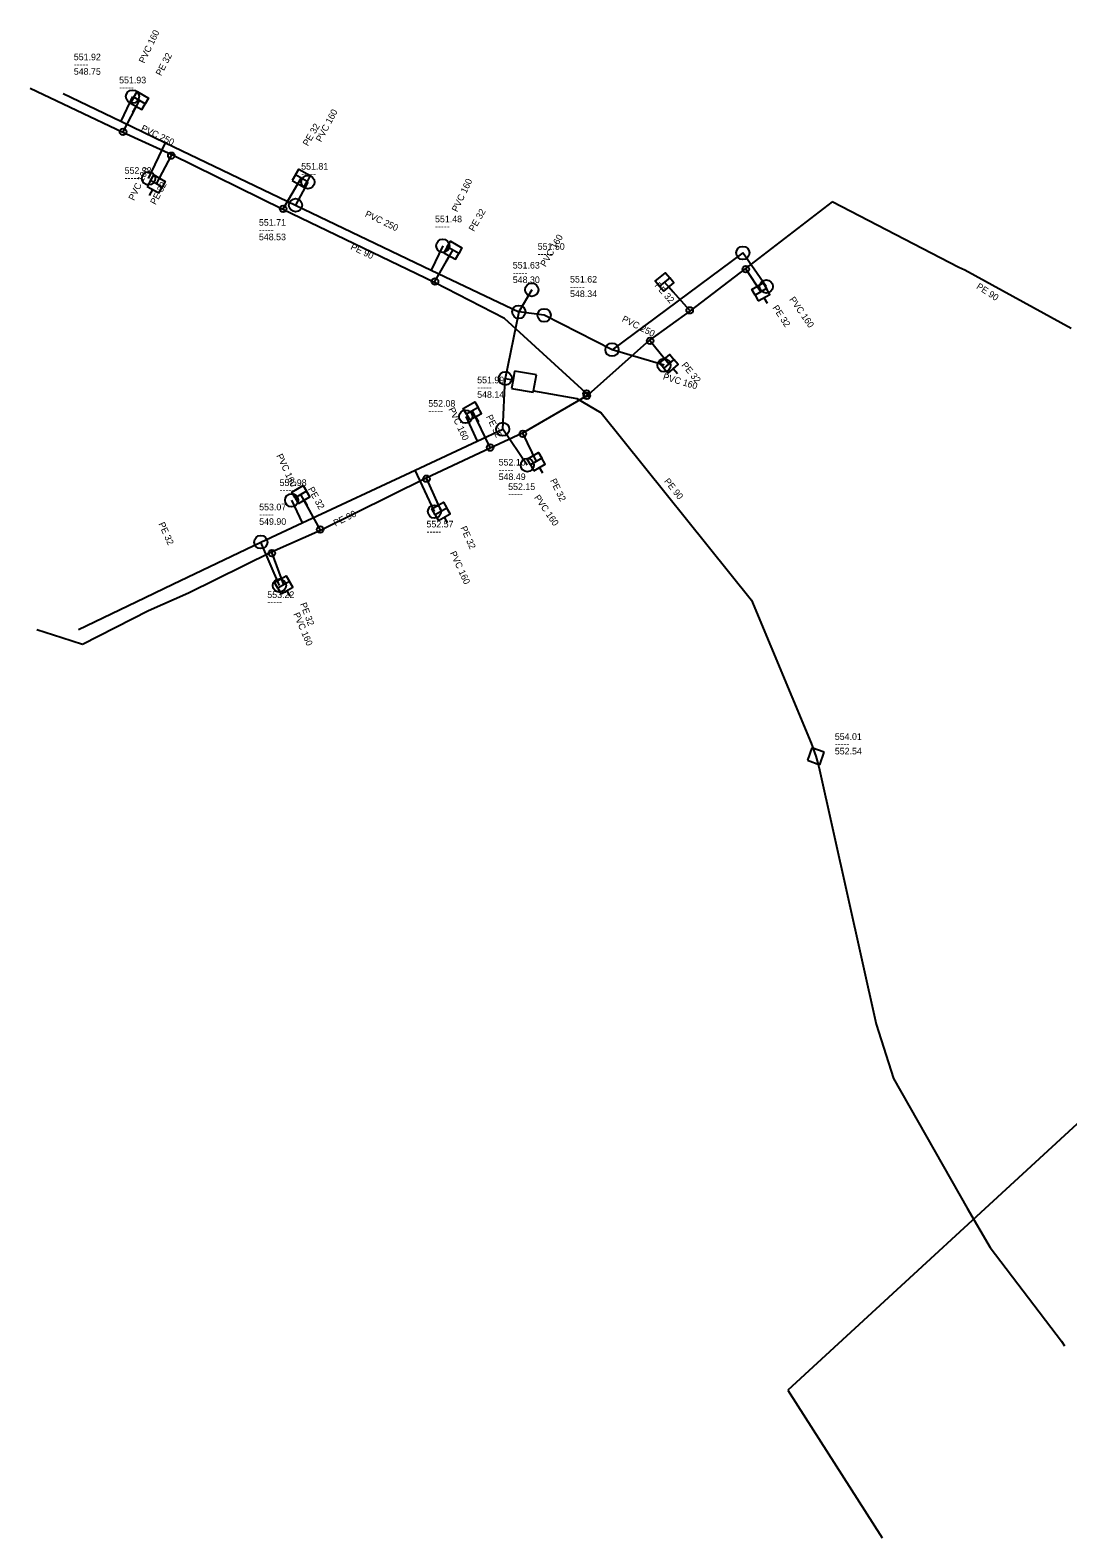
# Model space of a CAD drawing. Extents: x -701133 to -700495, y -1142806 to -1142020.
# Drawn here: x -701133 to -700975.9, y -1142805.5 to -1142577.3 of the extents above; entities that cross this region are included whole.
import ezdxf

# ---------------------------------------------------------------- set-up
doc = ezdxf.new("R2010")
doc.units = 0
doc.layers.add('Level 0', color=7, linetype='Continuous')

msp = doc.modelspace()

# ---------------------------------------------------------------- linework, layer by layer
at = {"layer": 'Level 0'}
for p, q in [((-701118.97, -1142592.8), (-701133, -1142586.12)), ((-701128.01, -1142586.91), (-701119.29, -1142591.1)), ((-701117.5, -1142587.37), (-701119.29, -1142591.1)), ((-701118.94, -1142592.7), (-701116.45, -1142587.97)), ((-701117.45, -1142589.7), (-701116.95, -1142588.84)), ((-701119.29, -1142591.1), (-701112.49, -1142594.36)), ((-701118.97, -1142592.8), (-701118.94, -1142592.7)), ((-701111.56, -1142596.18), (-701118.97, -1142592.8)), ((-701115.07, -1142599.74), (-701112.49, -1142594.36)), ((-701112.49, -1142594.36), (-701092.82, -1142603.8)), ((-701111.63, -1142596.3), (-701113.91, -1142600.58)), ((-701111.56, -1142596.18), (-701111.63, -1142596.3)), ((-701094.74, -1142604.44), (-701111.56, -1142596.18)), ((-701094.69, -1142604.34), (-701091.96, -1142599.7)), ((-701092.96, -1142601.43), (-701092.46, -1142600.57)), ((-701090.95, -1142600.3), (-701092.82, -1142603.8)), ((-701114.91, -1142602.31), (-701114.41, -1142601.45)), ((-701011.59, -1142603.29), (-701024.73, -1142613.38)), ((-700992.42, -1142613.21), (-701011.59, -1142603.29)), ((-701094.74, -1142604.44), (-701094.69, -1142604.34)), ((-701071.77, -1142615.48), (-701094.74, -1142604.44)), ((-701092.82, -1142603.8), (-701072.3, -1142613.62)), ((-701070.54, -1142609.94), (-701072.3, -1142613.62)), ((-701071.72, -1142615.37), (-701069, -1142610.62)), ((-701070, -1142612.35), (-701069.5, -1142611.49)), ((-701025.11, -1142611.03), (-701044.92, -1142625.68)), ((-701021.57, -1142616.1), (-701025.11, -1142611.03)), ((-701072.3, -1142613.62), (-701059.03, -1142619.96)), ((-701024.73, -1142613.38), (-701033.09, -1142619.81)), ((-701024.73, -1142613.38), (-701024.67, -1142613.48)), ((-701024.67, -1142613.48), (-701022.4, -1142616.93)), ((-700991.53, -1142613.66), (-700992.42, -1142613.21)), ((-700975.42, -1142622.48), (-700991.53, -1142613.66)), ((-701071.77, -1142615.48), (-701071.72, -1142615.37)), ((-701061.18, -1142620.95), (-701071.77, -1142615.48)), ((-701057.07, -1142616.6), (-701059.03, -1142619.96)), ((-701033.16, -1142619.72), (-701036.96, -1142615.43)), ((-701035.67, -1142616.96), (-701036.32, -1142616.2)), ((-701021.4, -1142618.66), (-701021.9, -1142617.8)), ((-701049.51, -1142631.63), (-701061.18, -1142620.95)), ((-701059.03, -1142619.96), (-701061.07, -1142630.02)), ((-701055.18, -1142620.47), (-701059.03, -1142619.96)), ((-701044.92, -1142625.68), (-701055.18, -1142620.47)), ((-701033.09, -1142619.81), (-701039.22, -1142624.24)), ((-701033.09, -1142619.81), (-701033.16, -1142619.72)), ((-701039.22, -1142624.24), (-701048.54, -1142632.52)), ((-701037.04, -1142628.03), (-701044.92, -1142625.68)), ((-701039.22, -1142624.24), (-701039.15, -1142624.34)), ((-701039.15, -1142624.34), (-701036.31, -1142627.82)), ((-701035.02, -1142629.35), (-701035.67, -1142628.59)), ((-701061.47, -1142637.72), (-701061.07, -1142630.02)), ((-701061.07, -1142630.02), (-701059.9, -1142630.24)), ((-701059.9, -1142630.24), (-701060.12, -1142631.53)), ((-701059.67, -1142628.95), (-701059.9, -1142630.24)), ((-701056.37, -1142629.48), (-701059.67, -1142628.95)), ((-701056.79, -1142631.9), (-701056.37, -1142629.48)), ((-701060.12, -1142631.53), (-701056.83, -1142632.11)), ((-701048.72, -1142632.67), (-701058.47, -1142638.29)), ((-701056.83, -1142632.11), (-701056.79, -1142631.9)), ((-701056.79, -1142631.9), (-701050.26, -1142633.04)), ((-701050.26, -1142633.04), (-701046.56, -1142635.24)), ((-701048.77, -1142632.31), (-701049.51, -1142631.63)), ((-701048.54, -1142632.52), (-701048.77, -1142632.31)), ((-701048.54, -1142632.52), (-701048.72, -1142632.67)), ((-701063.38, -1142640.5), (-701066.06, -1142634.94)), ((-701046.56, -1142635.24), (-701023.82, -1142663.57)), ((-701067.06, -1142635.81), (-701065.33, -1142639.52)), ((-701065.06, -1142636.67), (-701065.56, -1142635.81)), ((-701065.33, -1142639.52), (-701061.47, -1142637.72)), ((-701057.74, -1142643.14), (-701061.47, -1142637.72)), ((-701074.71, -1142643.9), (-701065.33, -1142639.52)), ((-701058.47, -1142638.29), (-701063.34, -1142640.59)), ((-701058.47, -1142638.29), (-701058.43, -1142638.4)), ((-701058.43, -1142638.4), (-701056.4, -1142642.62)), ((-701063.34, -1142640.59), (-701073.04, -1142645.1)), ((-701063.34, -1142640.59), (-701063.38, -1142640.5)), ((-701091.83, -1142651.88), (-701074.71, -1142643.9)), ((-701071.78, -1142650.19), (-701074.71, -1142643.9)), ((-701055.4, -1142644.35), (-701055.9, -1142643.49)), ((-701073.04, -1142645.1), (-701089.05, -1142653.03)), ((-701073.04, -1142645.1), (-701073, -1142645.2)), ((-701073, -1142645.2), (-701070.8, -1142650.15)), ((-701093.42, -1142648.47), (-701091.83, -1142651.88)), ((-701089.11, -1142652.91), (-701092.03, -1142647.59)), ((-701091.03, -1142649.32), (-701091.53, -1142648.46)), ((-701069.8, -1142651.88), (-701070.3, -1142651.02)), ((-701098.07, -1142654.79), (-701091.83, -1142651.88)), ((-701089.05, -1142653.03), (-701096.47, -1142656.34)), ((-701089.05, -1142653.03), (-701089.11, -1142652.91)), ((-701111.39, -1142661.17), (-701098.07, -1142654.79)), ((-701095.27, -1142661.36), (-701098.07, -1142654.79)), ((-701096.47, -1142656.34), (-701109.01, -1142662.54)), ((-701096.47, -1142656.34), (-701096.41, -1142656.47)), ((-701096.41, -1142656.47), (-701094.63, -1142661.27)), ((-701116.93, -1142663.82), (-701111.39, -1142661.17)), ((-701109.01, -1142662.54), (-701115.06, -1142665.2)), ((-701093.63, -1142663), (-701094.13, -1142662.14)), ((-701125.69, -1142668.02), (-701116.93, -1142663.82)), ((-701115.06, -1142665.2), (-701125.09, -1142670.29)), ((-701023.82, -1142663.57), (-701014.78, -1142685.23)), ((-701128.21, -1142669.31), (-701131.99, -1142668.08)), ((-701125.09, -1142670.29), (-701128.21, -1142669.31)), ((-701014.78, -1142685.23), (-701014.07, -1142687.22)), ((-701014.68, -1142685.94), (-701015.35, -1142687.83)), ((-701015.35, -1142687.83), (-701013.46, -1142688.5)), ((-701012.79, -1142686.61), (-701014.68, -1142685.94)), ((-701014.07, -1142687.22), (-701013.62, -1142688.8)), ((-701013.46, -1142688.5), (-701012.79, -1142686.61)), ((-701013.62, -1142688.8), (-701004.94, -1142727.79)), ((-700950.33, -1142720.59), (-701018.29, -1142783.18)), ((-701004.94, -1142727.79), (-701002.32, -1142736.02)), ((-701002.32, -1142736.02), (-700991.14, -1142755.65)), ((-700991.14, -1142755.65), (-700987.65, -1142761.58)), ((-700987.65, -1142761.58), (-700976.86, -1142775.77)), ((-700976.86, -1142775.77), (-700976.41, -1142776.48)), ((-701018.29, -1142783.18), (-701004.01, -1142805.53))]:
    msp.add_line(p, q, dxfattribs=at)
for points in [[(-701117.82, -1142588.34), (-701116.08, -1142589.34), (-701115.58, -1142588.47), (-701117.32, -1142587.47)], [(-701115.28, -1142600.95), (-701113.54, -1142601.95), (-701113.04, -1142601.08), (-701114.78, -1142600.08)], [(-701093.33, -1142600.07), (-701091.59, -1142601.07), (-701091.09, -1142600.2), (-701092.83, -1142599.2)], [(-701070.37, -1142610.99), (-701068.63, -1142611.99), (-701068.13, -1142611.12), (-701069.87, -1142610.12)], [(-701037.08, -1142616.84), (-701035.55, -1142615.55), (-701036.19, -1142614.79), (-701037.73, -1142616.07)], [(-701022.77, -1142618.3), (-701021.03, -1142617.3), (-701021.53, -1142616.43), (-701023.27, -1142617.43)], [(-701036.43, -1142629.23), (-701034.9, -1142627.94), (-701035.54, -1142627.18), (-701037.08, -1142628.46)], [(-701066.43, -1142636.31), (-701064.69, -1142635.31), (-701065.19, -1142634.44), (-701066.93, -1142635.44)], [(-701056.77, -1142643.99), (-701055.03, -1142642.99), (-701055.53, -1142642.12), (-701057.27, -1142643.12)], [(-701092.4, -1142648.96), (-701090.66, -1142647.96), (-701091.16, -1142647.09), (-701092.9, -1142648.09)], [(-701071.17, -1142651.52), (-701069.43, -1142650.52), (-701069.93, -1142649.65), (-701071.67, -1142650.65)], [(-701095, -1142662.64), (-701093.26, -1142661.64), (-701093.76, -1142660.77), (-701095.5, -1142661.77)]]:
    msp.add_lwpolyline(points, close=True, dxfattribs=at)
for points in [[(-701117.32, -1142587.47), (-701116.82, -1142586.6), (-701115.08, -1142587.6), (-701115.58, -1142588.47)], [(-701092.83, -1142599.2), (-701092.33, -1142598.33), (-701090.59, -1142599.33), (-701091.09, -1142600.2)], [(-701114.78, -1142600.08), (-701114.28, -1142599.21), (-701112.54, -1142600.21), (-701113.04, -1142601.08)], [(-701069.87, -1142610.12), (-701069.37, -1142609.25), (-701067.63, -1142610.25), (-701068.13, -1142611.12)], [(-701037.73, -1142616.07), (-701038.37, -1142615.31), (-701036.84, -1142614.02), (-701036.19, -1142614.79)], [(-701023.27, -1142617.43), (-701023.77, -1142616.56), (-701022.03, -1142615.56), (-701021.53, -1142616.43)], [(-701037.08, -1142628.46), (-701037.72, -1142627.7), (-701036.19, -1142626.41), (-701035.54, -1142627.18)], [(-701066.93, -1142635.44), (-701067.43, -1142634.57), (-701065.69, -1142633.57), (-701065.19, -1142634.44)], [(-701057.27, -1142643.12), (-701057.77, -1142642.25), (-701056.03, -1142641.25), (-701055.53, -1142642.12)], [(-701092.9, -1142648.09), (-701093.4, -1142647.22), (-701091.66, -1142646.22), (-701091.16, -1142647.09)], [(-701071.67, -1142650.65), (-701072.17, -1142649.78), (-701070.43, -1142648.78), (-701069.93, -1142649.65)], [(-701095.5, -1142661.77), (-701096, -1142660.9), (-701094.26, -1142659.9), (-701093.76, -1142660.77)]]:
    msp.add_lwpolyline(points, dxfattribs=at)
for centre, radius in [((-701117.5, -1142587.37), 1), ((-701118.94, -1142592.7), 0.5), ((-701111.63, -1142596.3), 0.5), ((-701115.07, -1142599.74), 1), ((-701090.95, -1142600.3), 1), ((-701092.82, -1142603.8), 1), ((-701094.69, -1142604.34), 0.5), ((-701070.54, -1142609.94), 1), ((-701025.11, -1142611.03), 1), ((-701071.72, -1142615.37), 0.5), ((-701024.67, -1142613.48), 0.5), ((-701057.07, -1142616.6), 1), ((-701021.57, -1142616.1), 1), ((-701059.03, -1142619.96), 1), ((-701055.18, -1142620.47), 1), ((-701033.16, -1142619.72), 0.5), ((-701039.15, -1142624.34), 0.5), ((-701044.92, -1142625.68), 1), ((-701037.04, -1142628.03), 1), ((-701061.07, -1142630.02), 1), ((-701048.77, -1142632.31), 0.5), ((-701048.72, -1142632.67), 0.5), ((-701067.06, -1142635.81), 1), ((-701061.47, -1142637.72), 1), ((-701063.38, -1142640.5), 0.5), ((-701058.43, -1142638.4), 0.5), ((-701057.74, -1142643.14), 1), ((-701073, -1142645.2), 0.5), ((-701093.42, -1142648.47), 1), ((-701071.78, -1142650.19), 1), ((-701098.07, -1142654.79), 1), ((-701089.11, -1142652.91), 0.5), ((-701096.41, -1142656.47), 0.5), ((-701095.27, -1142661.36), 1)]:
    msp.add_circle(centre, radius, dxfattribs=at)

# ---------------------------------------------------------------- texts
for s, rotation, p in [('PVC 160', 64.364, (-701115.71, -1142582.41)), ('PE 32', 62.236, (-701113.18, -1142584.31)), ('PVC 160', 61.885, (-701088.94, -1142594.33)), ('PVC 250', 334.386, (-701116.31, -1142592.49)), ('PE 32', 59.529, (-701090.95, -1142594.94)), ('PVC 160', 64.38, (-701117.27, -1142603.19)), ('PE 32', 61.955, (-701114.01, -1142603.82)), ('PVC 160', 64.44, (-701068.34, -1142604.91)), ('PVC 250', 334.463, (-701082.4, -1142605.47)), ('PE 32', 60.203, (-701065.81, -1142607.87)), ('PE 90', 334.33, (-701084.59, -1142610.43)), ('PVC 160', 59.744, (-701054.99, -1142613.22)), ('PE 32', 311.534, (-701038.54, -1142616.01)), ('PE 90', 326.957, (-700989.86, -1142616.35)), ('PE 32', 303.344, (-701020.68, -1142619.33)), ('PVC 160', 304.924, (-701018.13, -1142618.08)), ('PVC 250', 333.079, (-701043.52, -1142621.35)), ('PE 32', 309.218, (-701034.46, -1142628.04)), ('PVC 160', 343.394, (-701037.28, -1142630.17)), ('PVC 160', 295, (-701069.7, -1142634.68)), ('PE 32', 295.735, (-701064.01, -1142635.81)), ('PVC 160', 294.998, (-701095.75, -1142641.71)), ('PE 32', 298.761, (-701090.99, -1142646.77)), ('PE 32', 295.69, (-701054.32, -1142645.47)), ('PE 90', 308.753, (-701037.1, -1142645.62)), ('PVC 160', 304.535, (-701056.76, -1142648.06)), ('PE 90', 26.309, (-701086.79, -1142652.45)), ('PE 32', 294.192, (-701113.6, -1142652.04)), ('PE 32', 293.962, (-701067.89, -1142652.64)), ('PVC 160', 294.977, (-701069.5, -1142656.45)), ('PE 32', 290.346, (-701092.15, -1142664.16)), ('PVC 160', 293.083, (-701093.19, -1142665.69))]:
    msp.add_text(s, height=1, rotation=rotation, dxfattribs=at).set_placement(p)
for s, p in [('551.92', (-701126.39, -1142581.86)), ('548.75', (-701126.39, -1142584.06)), ('-----', (-701126.39, -1142582.96)), ('551.93', (-701119.53, -1142585.36)), ('-----', (-701119.53, -1142586.46)), ('552.32', (-701118.7, -1142599.05)), ('551.81', (-701091.97, -1142598.42)), ('-----', (-701091.97, -1142599.52)), ('-----', (-701118.7, -1142600.15)), ('551.71', (-701098.37, -1142606.91)), ('551.48', (-701071.71, -1142606.39)), ('548.53', (-701098.37, -1142609.11)), ('-----', (-701098.37, -1142608.01)), ('-----', (-701071.71, -1142607.49)), ('551.50', (-701056.17, -1142610.55)), ('551.63', (-701059.94, -1142613.39)), ('-----', (-701056.17, -1142611.65)), ('548.30', (-701059.94, -1142615.59)), ('-----', (-701059.94, -1142614.49)), ('551.62', (-701051.27, -1142615.51)), ('548.34', (-701051.27, -1142617.71)), ('-----', (-701051.27, -1142616.61)), ('551.99', (-701065.33, -1142630.76)), ('552.08', (-701072.73, -1142634.31)), ('548.14', (-701065.33, -1142632.96)), ('-----', (-701065.33, -1142631.86)), ('-----', (-701072.73, -1142635.41)), ('552.10', (-701062.08, -1142643.21)), ('548.49', (-701062.08, -1142645.41)), ('-----', (-701062.08, -1142644.31)), ('552.98', (-701095.24, -1142646.31)), ('-----', (-701095.24, -1142647.41)), ('552.15', (-701060.64, -1142646.91)), ('553.07', (-701098.33, -1142649.99)), ('-----', (-701060.64, -1142648.01)), ('549.90', (-701098.33, -1142652.19)), ('-----', (-701098.33, -1142651.09)), ('552.57', (-701073, -1142652.58)), ('-----', (-701073, -1142653.68)), ('553.22', (-701097.1, -1142663.26)), ('-----', (-701097.1, -1142664.36)), ('554.01', (-701011.19, -1142684.74)), ('-----', (-701011.19, -1142685.84)), ('552.54', (-701011.19, -1142686.94))]:
    msp.add_text(s, height=1, dxfattribs=at).set_placement(p)

doc.saveas('drawing.dxf')
